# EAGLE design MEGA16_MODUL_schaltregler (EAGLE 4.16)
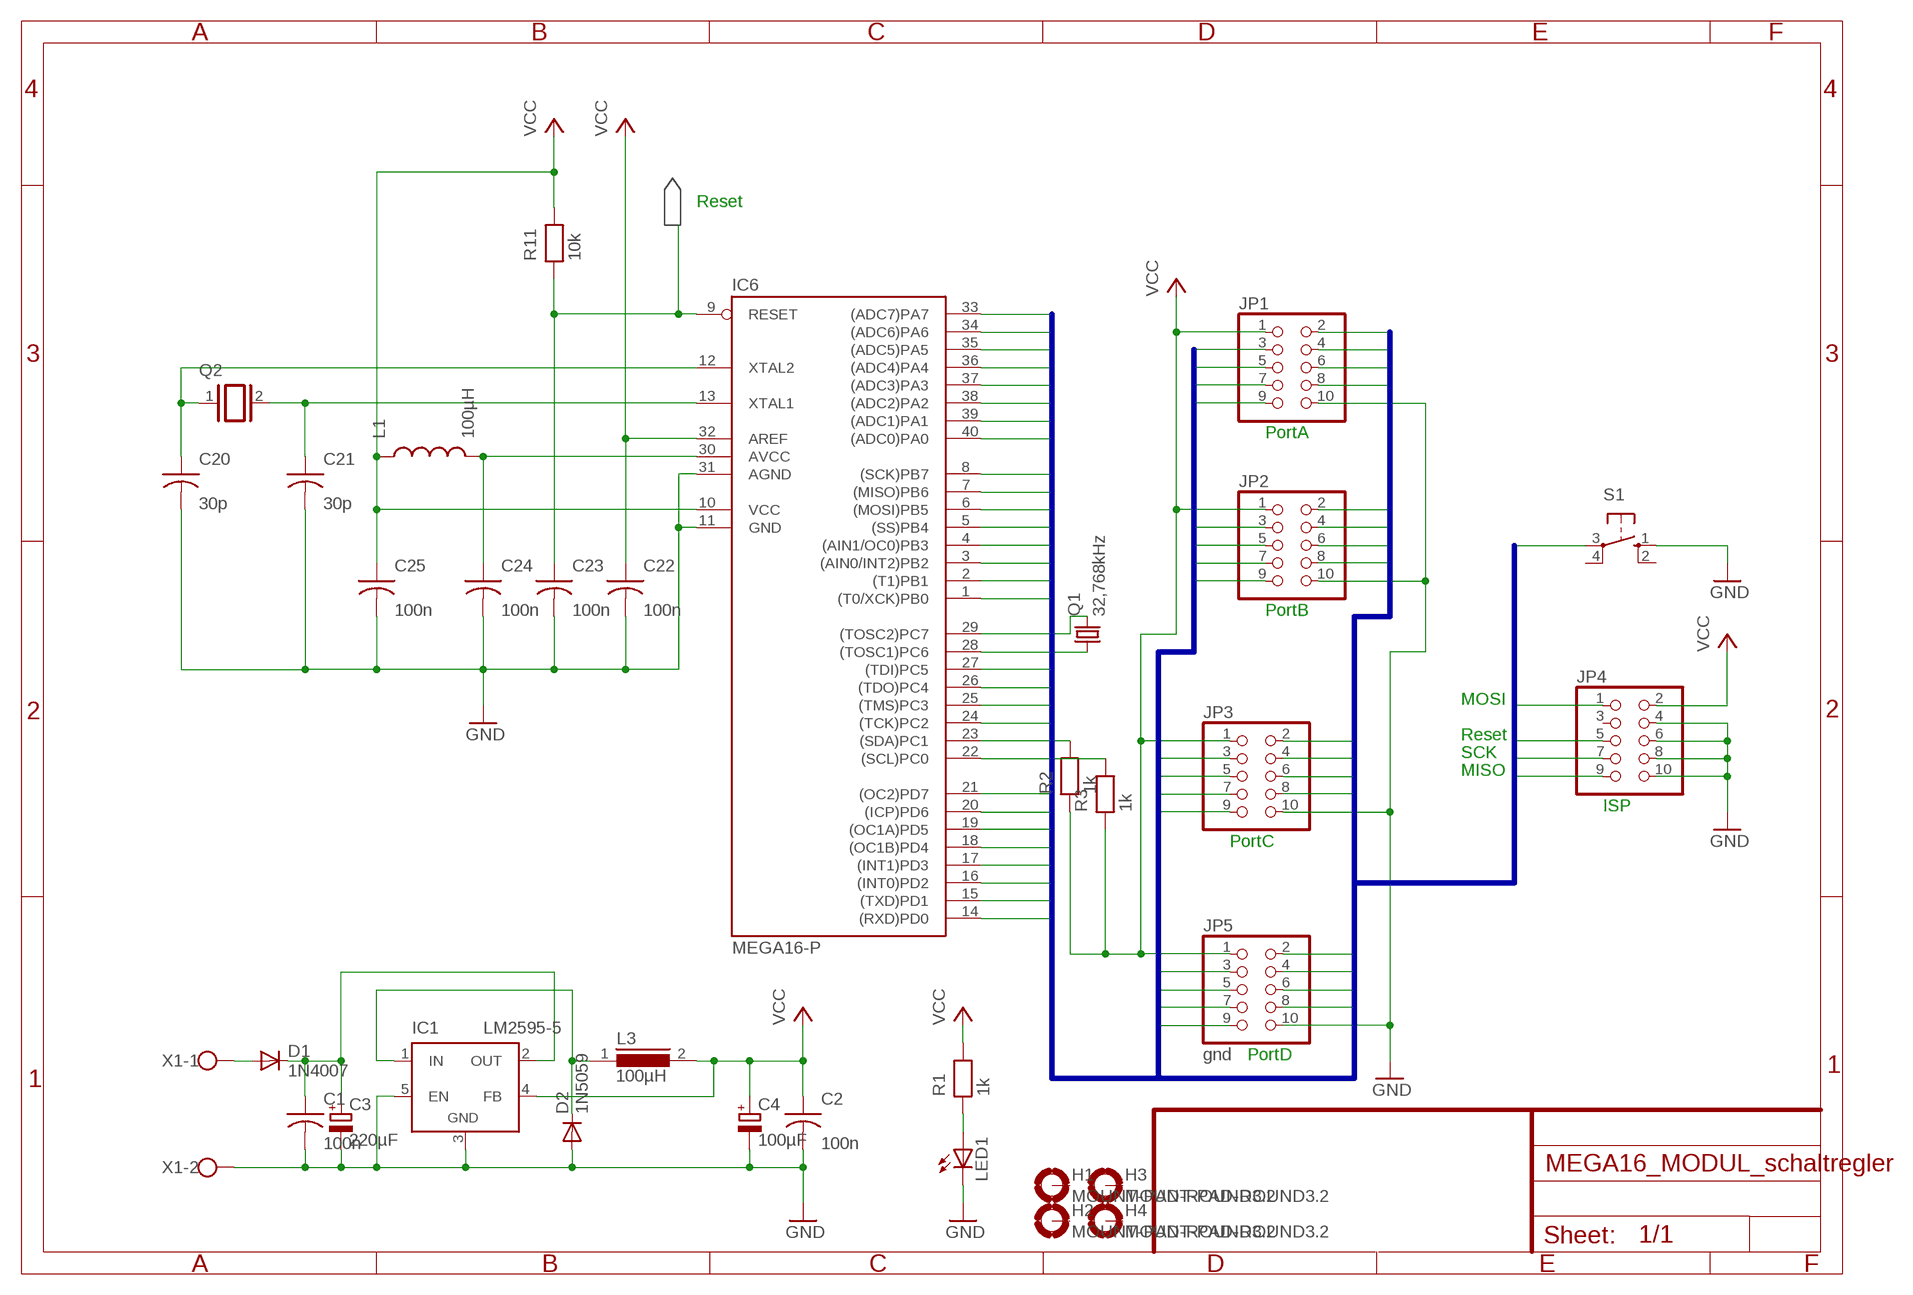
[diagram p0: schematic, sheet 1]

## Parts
C1  100n  CAP-2,5  [C-2,5]
C2  100n  CAP-2,5  [C-2,5]
C3  220µF  CPOL-EUE5-8.5  [E5-8,5]
C4  100µF  CPOL-EUE2,5-6E  [E2,5-6E]
C20  30p  CAP-2,5  [C-2,5]
C21  30p  CAP-2,5  [C-2,5]
C22  100n  CAP-2,5  [C-2,5]
C23  100n  CAP-2,5  [C-2,5]
C24  100n  CAP-2,5  [C-2,5]
C25  100n  CAP-2,5  [C-2,5]
D1  1N4007  1N4004  [DO41-10]
D2  1N5059  [DO204-10]
H1  MOUNT-PAD-ROUND3.2  [3,2-PAD]
H2  MOUNT-PAD-ROUND3.2  [3,2-PAD]
H3  MOUNT-PAD-ROUND3.2  [3,2-PAD]
H4  MOUNT-PAD-ROUND3.2  [3,2-PAD]
IC1  LM2595-5  LM2596TV  [TO220-51]
IC6  MEGA16-P  [DIL40]
JP1  PINHD-2X5  [2X05]
JP2  PINHD-2X5  [2X05]
JP3  PINHD-2X5  [2X05]
JP4  PINHD-2X5  [2X05]
JP5  gnd  PINHD-2X5  [2X05]
L1  100µH  L-10  [L-10]
L3  100µH  SFT830D  [SFT830D]
LED1  LEDB152  [Q62902-B152]
Q1  32,768kHz  CRYTALTC26H  [TC26H]
Q2  XTAL/S  [QS]
R1  1k  RESEU-S2,5  [RS-2,5]
R2  1k  RESEU-S2,5  [RS-2,5]
R3  1k  RESEU-S2,5  [RS-2,5]
R11  10k  RESEU-S2,5  [RS-2,5]
S1  10-XX  [B3F-10XX]
X1  W237-02P  [W237-132]

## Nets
GND: C1.2 C2.2 C3.- C4.- C20.2 C21.2 C22.2 C23.2 C24.2 C25.2 D2.A IC1.3(GND) IC1.5(EN) IC6.11(GND) IC6.31(AGND) JP1.10 JP2.10 JP3.10 JP4.4 JP4.6 JP4.8 JP4.10 JP5.10 LED1.K(C) S1.1(S) X1.2
N$1: D1.A X1.1
N$2: C1.1 C3.+ D1.C IC1.2(OUT)
N$3: D2.C IC1.1(IN) L3.1
N$5: LED1.A R1.1
N$39: C20.1 IC6.12(XTAL2) Q2.1
N$49: C21.1 IC6.13(XTAL1) Q2.2
N$59: C24.1 IC6.30(AVCC) L1.2
PA0: IC6.40((ADC0)PA0) JP1.2
PA1: IC6.39((ADC1)PA1) JP1.3
PA2: IC6.38((ADC2)PA2) JP1.4
PA3: IC6.37((ADC3)PA3) JP1.5
PA4: IC6.36((ADC4)PA4) JP1.6
PA5: IC6.35((ADC5)PA5) JP1.7
PA6: IC6.34((ADC6)PA6) JP1.8
PA7: IC6.33((ADC7)PA7) JP1.9
PB0: IC6.1((T0/XCK)PB0) JP2.2
PB1: IC6.2((T1)PB1) JP2.3
PB2: IC6.3((AIN0/INT2)PB2) JP2.4
PB3: IC6.4((AIN1/OC0)PB3) JP2.5
PB4: IC6.5((SS)PB4) JP2.6
PB5: IC6.6((MOSI)PB5) JP2.7 JP4.1
PB6: IC6.7((MISO)PB6) JP2.8 JP4.9
PB7: IC6.8((SCK)PB7) JP2.9 JP4.7
PC0: IC6.22((SCL)PC0) JP3.2 R3.2
PC1: IC6.23((SDA)PC1) JP3.3 R2.2
PC2: IC6.24((TCK)PC2) JP3.4
PC3: IC6.25((TMS)PC3) JP3.5
PC4: IC6.26((TDO)PC4) JP3.6
PC5: IC6.27((TDI)PC5) JP3.7
PC6: IC6.28((TOSC1)PC6) JP3.8 Q1.1
PC7: IC6.29((TOSC2)PC7) JP3.9 Q1.2
PD0: IC6.14((RXD)PD0) JP5.2
PD1: IC6.15((TXD)PD1) JP5.3
PD2: IC6.16((INT0)PD2) JP5.4
PD3: IC6.17((INT1)PD3) JP5.5
PD4: IC6.18((OC1B)PD4) JP5.6
PD5: IC6.19((OC1A)PD5) JP5.7
PD6: IC6.20((ICP)PD6) JP5.8
PD7: IC6.21((OC2)PD7) JP5.9
RESET: C23.1 IC6.9(RESET) JP4.5 R11.1 S1.3(P)
VCC: C2.1 C4.+ C22.1 C25.1 IC1.4(FB) IC6.10(VCC) IC6.32(AREF) JP1.1 JP2.1 JP3.1 JP4.2 JP5.1 L1.1 L3.2 R1.2 R2.1 R3.1 R11.2
Unconnected: H1.B3,2(MOUNT) H2.B3,2(MOUNT) H3.B3,2(MOUNT) H4.B3,2(MOUNT) JP4.3 S1.2(S1) S1.4(P1)

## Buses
B$1

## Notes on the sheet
- Reset
- PortA
- PortB
- MOSI
- Reset
- SCK
- MISO
- ISP
- PortC
- PortD

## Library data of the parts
C1 C2 C20-C25 = discrete:CAP-2,5
C3 C4 = rcl:CPOL-EU: POLARIZED CAPACITOR, European symbol
D1 = diode:1N4004: DIODE
D2 = diode:1N5059: DIODE
H1-H4 = holes:MOUNT-PAD-ROUND: MOUNTING PAD, round
IC1 = linear:LM2596T: STEP-DOWN VOLTAGE REGULATOR
IC6 = avr:MEGA16-P: MICROCONTROLLER 16 Kbytes FLASH 1 kbytes SRAM 512 bytes EEPROM USART 8-channel 10 bit ADC
JP1-JP5 = pinhead:PINHD-2X5: PIN HEADER
L1 = discrete:L-10
L3 = inductors:SFT830D: INDUCTOR
LED1 = led:LED: LED
Q1 = crystal:CRYTAL: CRYSTAL
Q2 = special:XTAL/S: CRYSTAL
R1-R3 R11 = discrete:RESEU-S2,5
S1 = switch-omron:10-XX: OMRON SWITCH
X1 = con-wago-508:W237-02P: WAGO SREW CLAMP

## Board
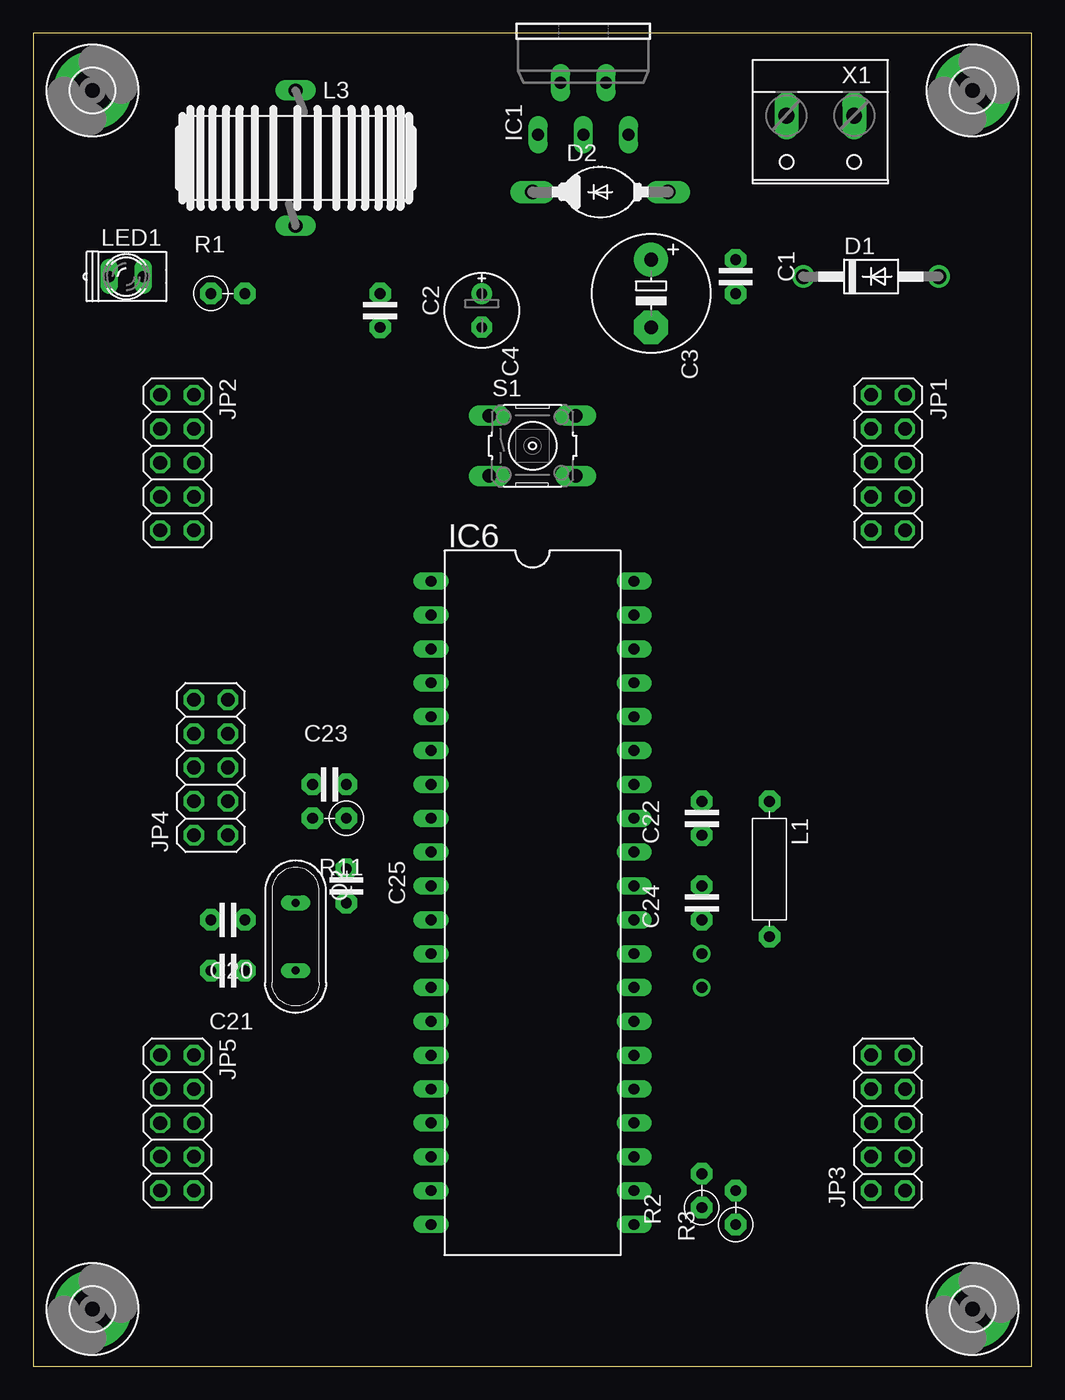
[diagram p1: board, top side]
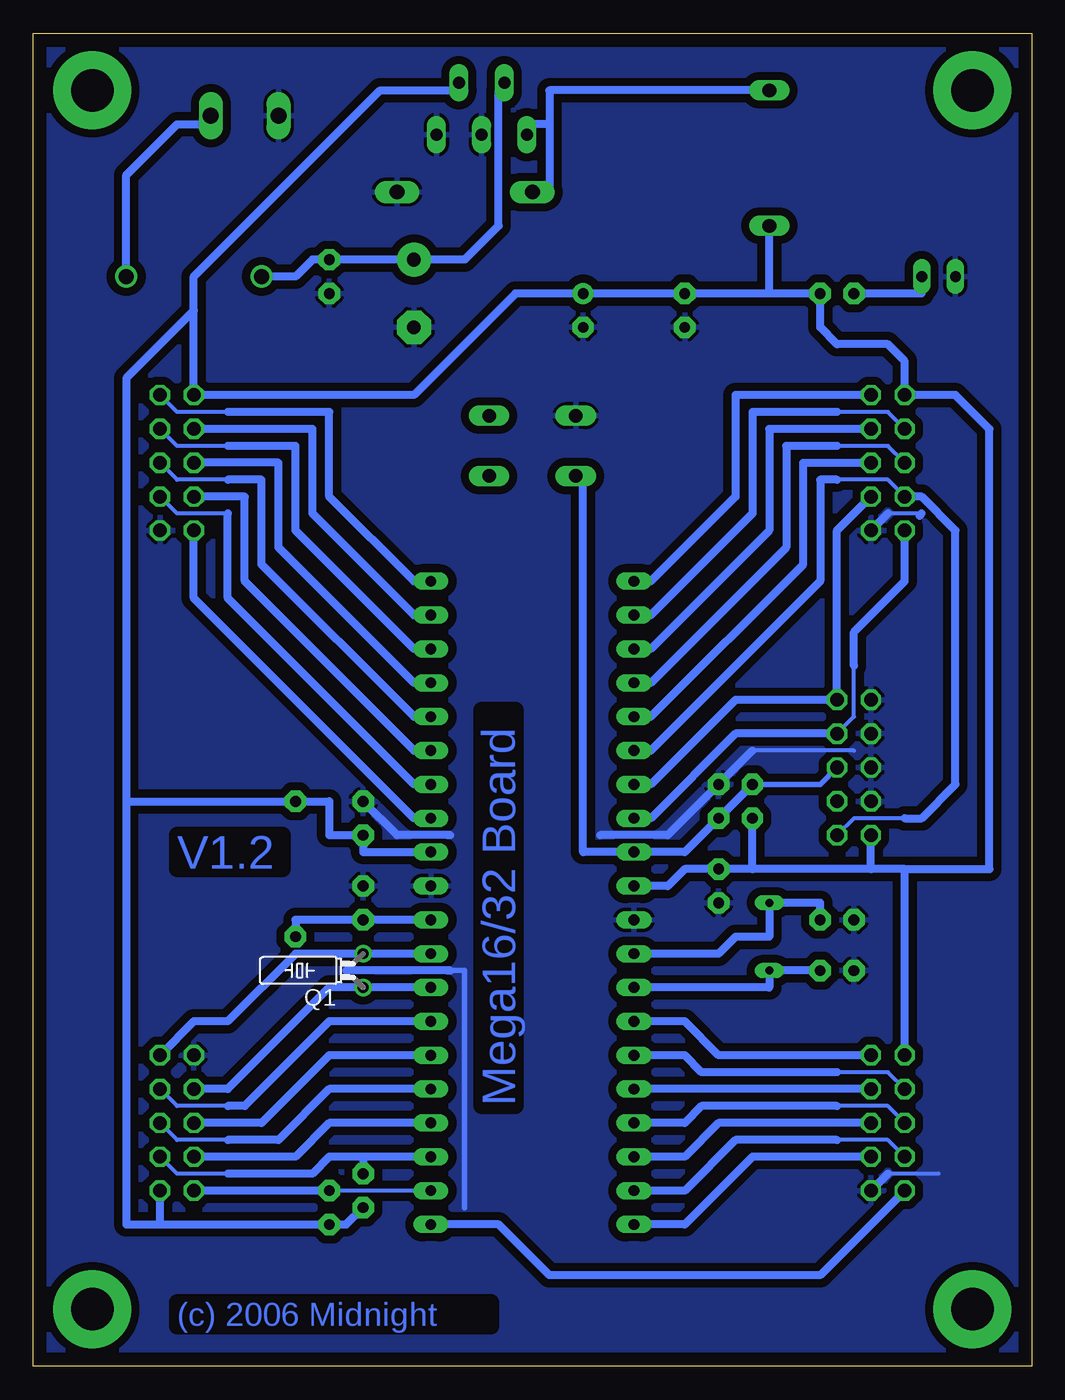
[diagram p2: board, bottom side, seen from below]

Size 74.91 x 100 mm. Coordinates in mm from the lower left corner, seen from the top.
Outline: 0,0 74.91,0 74.91,100 0,100 0,0
Copper layers (1*16): Top 0.035mm / dielectric 1.5mm / Bottom 0.035mm
Design rules "default": minimum track width 24mil, minimum drill 24mil, track to track 8mil, track to pad 8mil, pad to pad 8mil, via to via 8mil, smd to smd 8mil, copper to edge 40mil, drill to drill 8mil, minimum pad ring 10mil, minimum via ring 8mil, stop-mask expansion 4mil, vias tented up to drill 0mil, thermal gap 10mil

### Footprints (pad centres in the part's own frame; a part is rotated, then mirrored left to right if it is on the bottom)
C-2,5 = drill 0.813 pad 1.6 octagon: 1 -1.27,0; 2 1.27,0
E5-8,5 = drill 1.016 pad 2.54 round: + -2.54,0 | drill 1.016 pad 2.54 octagon: - 2.54,0
E2,5-6E = drill 0.813 pad 1.575 round: + -1.27,0 | drill 0.813 pad 1.575 octagon: - 1.27,0
DO41-10 = drill 1.118 round: A 5.08,0; C -5.08,0
DO204-10 = drill 1.118 long: A 5.08,0; C -5.08,0
3,2-PAD = drill 3.2 pad 5.842 round: B3,2 0,0
TO220-51 = drill 0.9 long: 1 -3.4,-8.4; 2 -1.7,-4.5; 3 0,-8.4; 4 1.7,-4.5; 5 3.4,-8.4
DIL40 = drill 0.813 long: 1 -24.13,-7.62; 2 -21.59,-7.62; 3 -19.05,-7.62; 4 -16.51,-7.62; 5 -13.97,-7.62; 6 -11.43,-7.62; 7 -8.89,-7.62; 8 -6.35,-7.62; 9 -3.81,-7.62; 10 -1.27,-7.62; 11 1.27,-7.62; 12 3.81,-7.62; 13 6.35,-7.62; 14 8.89,-7.62; 15 11.43,-7.62; 16 13.97,-7.62; 17 16.51,-7.62; 18 19.05,-7.62; 19 21.59,-7.62; 20 24.13,-7.62; 21 24.13,7.62; 22 21.59,7.62; 23 19.05,7.62; 24 16.51,7.62; 25 13.97,7.62; 26 11.43,7.62; 27 8.89,7.62; 28 6.35,7.62; 29 3.81,7.62; 30 1.27,7.62; 31 -1.27,7.62; 32 -3.81,7.62; 33 -6.35,7.62; 34 -8.89,7.62; 35 -11.43,7.62; 36 -13.97,7.62; 37 -16.51,7.62; 38 -19.05,7.62; 39 -21.59,7.62; 40 -24.13,7.62
2X05 = drill 1.016 octagon: 1 -5.08,-1.27; 2 -5.08,1.27; 3 -2.54,-1.27; 4 -2.54,1.27; 5 0,-1.27; 6 0,1.27; 7 2.54,-1.27; 8 2.54,1.27; 9 5.08,-1.27; 10 5.08,1.27
L-10 = drill 0.813 pad 1.6 octagon: 1 -5.08,0; 2 5.08,0
SFT830D = drill 1.016 long: 1 -5.08,0; 2 5.08,0
Q62902-B152 = drill 0.813 long: A 1.27,0; K -1.27,0
TC26H = drill 0.813 round: 1 -1.27,0; 2 1.27,0
QS = drill 0.61 long: 1 -2.54,0; 2 2.54,0
RS-2,5 = drill 0.813 pad 1.6 octagon: 1 0,0; 2 2.54,0
B3F-10XX = drill 1.016 long: 1 -3.251,2.261; 2 3.251,2.261; 3 -3.251,-2.261; 4 3.251,-2.261
W237-132 = drill 1.194 long: 1 -2.54,-0.635; 2 2.54,-0.635

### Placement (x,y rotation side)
C1  52.7,81.75 270 top
C2  26.03,79.21 270 top
C3  46.35,80.48 270 top
C4  33.65,79.21 270 top
C20  14.6,33.49 180 top
C21  14.6,29.68 180 top
C22  50.16,41.11 90 top
C23  22.22,43.65 0 top
C24  50.16,34.76 90 top
C25  23.49,36.03 270 top
D1  62.86,81.75 0 top
D2  42.54,88.1 0 top
H1  4.44,4.28 0 top
H2  70.48,4.28 0 top
H3  4.44,95.72 0 top
H4  70.48,95.72 0 top
IC1  41.27,100.8 0 top
IC6  37.46,34.76 270 top
JP1  64.13,67.78 270 top
JP2  10.79,67.78 270 top
JP3  64.13,18.25 90 top
JP4  13.33,44.92 90 top
JP5  10.79,18.25 270 top
L1  55.24,37.3 270 top
L3  19.68,90.64 270 top
LED1  6.98,81.75 0 top
Q1  50.16,29.68 90 bottom
Q2  19.68,32.22 270 top
R1  13.33,80.48 0 top
R2  50.16,11.9 90 top
R3  52.7,10.63 90 top
R11  23.49,41.11 180 top
S1  37.46,69.05 0 top
X1  59.05,93.18 180 top

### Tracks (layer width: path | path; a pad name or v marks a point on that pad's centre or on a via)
GND
  Bottom 0.305: 8.25,63.97 10.79,63.97 | 13.33,46.19 20.95,46.19 | 6.98,14.44 10.79,14.44
  Bottom 0.406: 43.61,29.68 42.54,29.68 42.54,11.9
  Bottom 0.61: 51.43,29.68 43.81,29.68 43.61,29.68 | 20.95,46.19 C23.2 27.3,39.84 32.38,39.84 | 10.79,14.44 JP5.10 | 10.79,63.97 JP2.10 | 8.4,63.81 8.25,63.97 | C22.2 47.62,39.84 43.81,39.84 43.61,39.84
  pour Bottom (isolate 0.61): 0.63,99.53 74.29,99.53 74.29,0.47 0.63,0.47
N$1
  Bottom 0.61: D1.A 67.94,89.37 64.13,93.18 61.59,93.18 X1.1
N$2
  Bottom 0.61: D1.C 55.24,81.75 53.97,83.02 C1.1 C3.+ 42.54,83.02 40,85.56 40,95.72 IC1.2
N$3
  Bottom 0.61: 36.19,93.18 36.19,95.72 L3.1 | 36.19,93.18 36.19,88.1 D2.C | 36.19,93.18 37.46,93.18 IC1.1
N$5
  Bottom 0.61: R1.1 8.25,80.48 LED1.A
N$39
  Bottom 0.61: C20.1 15.87,34.76 Q2.1 19.68,32.22 22.22,32.22 23.49,30.95 IC6.12
N$49
  Bottom 0.61: C21.1 Q2.2 19.68,28.41 IC6.13
N$59
  Bottom 0.61: IC6.30 C24.1 55.24,33.49 L1.2
PA0
  Bottom 0.305: JP1.2 64.13,71.59 60.32,71.59
  Bottom 0.61: IC6.40 46.35,58.89 52.7,65.24 52.7,71.59 60.32,71.59
PA1
  Bottom 0.61: JP1.3 53.97,70.32 53.97,63.97 46.35,56.35 IC6.39
PA2
  Bottom 0.305: JP1.4 64.13,69.05 60.32,69.05
  Bottom 0.61: IC6.38 46.35,53.81 55.24,62.7 55.24,69.05 60.32,69.05
PA3
  Bottom 0.61: JP1.5 56.51,67.78 56.51,61.43 46.35,51.27 IC6.37
PA4
  Bottom 0.305: JP1.6 64.13,66.51 60.32,66.51
  Bottom 0.61: IC6.36 46.35,48.73 57.78,60.16 57.78,66.51 60.32,66.51
PA5
  Bottom 0.61: JP1.7 59.05,65.24 59.05,58.89 46.35,46.19 IC6.35
PA6
  Bottom 0.305: JP1.8 64.13,63.97 60.32,63.97
  Bottom 0.61: 60.32,63.97 60.32,57.62 46.35,43.65 IC6.34
PA7
  Bottom 0.61: JP1.9 62.86,57.62 46.35,41.11 IC6.33
PB0
  Bottom 0.61: JP2.2 22.22,72.86 22.22,65.24 28.57,58.89 IC6.1
PB1
  Bottom 0.305: JP2.3 10.79,71.59 14.6,71.59
  Bottom 0.61: IC6.2 28.57,56.35 20.95,63.97 20.95,71.59 14.6,71.59
PB2
  Bottom 0.61: JP2.4 19.68,70.32 19.68,62.7 28.57,53.81 IC6.3
PB3
  Bottom 0.305: JP2.5 10.79,69.05 14.6,69.05
  Bottom 0.61: IC6.4 28.57,51.27 18.41,61.43 18.41,69.05 14.6,69.05
PB4
  Bottom 0.61: JP2.6 17.14,67.78 17.14,60.16 28.57,48.73 IC6.5
PB5
  Bottom 0.305: JP4.1 13.33,41.11 9.52,41.11 | JP2.7 10.79,66.51 14.6,66.51
  Bottom 0.61: IC6.6 28.57,46.19 15.87,58.89 15.87,66.51 14.6,66.51 | JP2.7 8.25,65.24 5.71,62.7 5.71,43.65 8.25,41.11 9.52,41.11
PB6
  Bottom 0.61: IC6.7 28.57,43.65 22.22,50 JP4.9 14.6,62.7 JP2.8
PB7
  Bottom 0.305: 13.33,52.54 13.33,48.73 JP4.7
  Bottom 0.61: JP4.7 22.22,47.46 28.57,41.11 IC6.8 | 13.33,52.54 13.33,55.08 9.52,58.89 JP2.9
PC0
  Bottom 0.305: IC6.22 R3.2
  Bottom 0.61: R3.2 JP3.2
PC1
  Bottom 0.305: JP3.3 64.13,14.44 60.32,14.44
  Bottom 0.61: IC6.23 50.16,15.71 | 50.16,15.71 52.7,15.71 53.97,14.44 60.32,14.44 | 50.16,15.71 R2.2
PC2
  Bottom 0.61: IC6.24 52.7,18.25 55.24,15.71 JP3.4
PC3
  Bottom 0.305: JP3.5 64.13,16.98 60.32,16.98
  Bottom 0.61: IC6.25 52.7,20.79 56.51,16.98 60.32,16.98
PC4
  Bottom 0.61: IC6.26 52.7,23.33 57.78,18.25 JP3.6
PC5
  Bottom 0.305: JP3.7 64.13,19.52 60.32,19.52
  Bottom 0.61: IC6.27 52.7,25.87 59.05,19.52 60.32,19.52
PC6
  Bottom 0.61: IC6.28 Q1.1 52.7,28.41 60.32,20.79 JP3.8
PC7
  Bottom 0.61: JP3.9 62.86,25.87 60.32,25.87 55.24,30.95 Q1.2 IC6.29
PD0
  Bottom 0.61: JP5.2 23.49,23.33 26.03,25.87 IC6.14
PD1
  Bottom 0.305: 14.6,22.06 10.79,22.06 JP5.3
  Bottom 0.61: IC6.15 26.03,23.33 24.76,22.06 14.6,22.06
PD2
  Bottom 0.61: JP5.4 IC6.16
PD3
  Bottom 0.305: 14.6,19.52 10.79,19.52 JP5.5
  Bottom 0.61: IC6.17 26.03,18.25 24.76,19.52 14.6,19.52
PD4
  Bottom 0.61: JP5.6 23.49,18.25 26.03,15.71 IC6.18
PD5
  Bottom 0.305: 14.6,16.98 10.79,16.98 JP5.7
  Bottom 0.61: IC6.19 26.03,13.17 22.22,16.98 14.6,16.98
PD6
  Bottom 0.61: JP5.8 20.95,15.71 26.03,10.63 IC6.20
PD7
  Bottom 0.61: IC6.21 40,10.63 36.19,6.82 15.87,6.82 JP5.9
RESET
  Bottom 0.406: 26.03,38.57 C23.1 15.87,43.65 JP4.5
  Bottom 0.61: C23.1 R11.1 26.03,38.57 IC6.9 33.65,38.57 33.65,66.51 S1.3
VCC
  Bottom 0.61: 9.52,37.3 12.06,37.3 | 12.06,37.3 JP4.2 | 20.95,37.3 R11.2 | 12.06,37.3 20.95,37.3 | 65.4,10.63 JP3.1 | 65.4,10.63 R3.1 51.43,10.63 R2.1 | 9.52,37.3 3.17,37.3 3.17,70.32 5.71,72.86 JP2.1 9.52,75.4 10.79,76.67 14.6,76.67 15.87,77.94 R1.2 19.68,80.48 | 19.68,80.48 C2.1 C4.+ 38.73,80.48 46.35,72.86 JP1.1 62.86,79.21 | 62.86,79.21 62.86,81.75 48.89,95.72 42.54,95.72 IC1.4 | 67.94,42.38 67.94,74.13 62.86,79.21 | 67.94,42.38 L1.1 52.7,42.38 52.7,39.84 C22.1 50.16,38.57 IC6.32 | 67.94,42.38 67.94,10.63 65.4,10.63 | JP5.1 9.52,37.3 | 20.95,37.3 C25.1 26.03,37.3 27.3,36.03 IC6.10 | 19.68,80.48 L3.2

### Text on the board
Bottom: V1.2 | Mega16/32 Board | (c) 2006 Midnight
